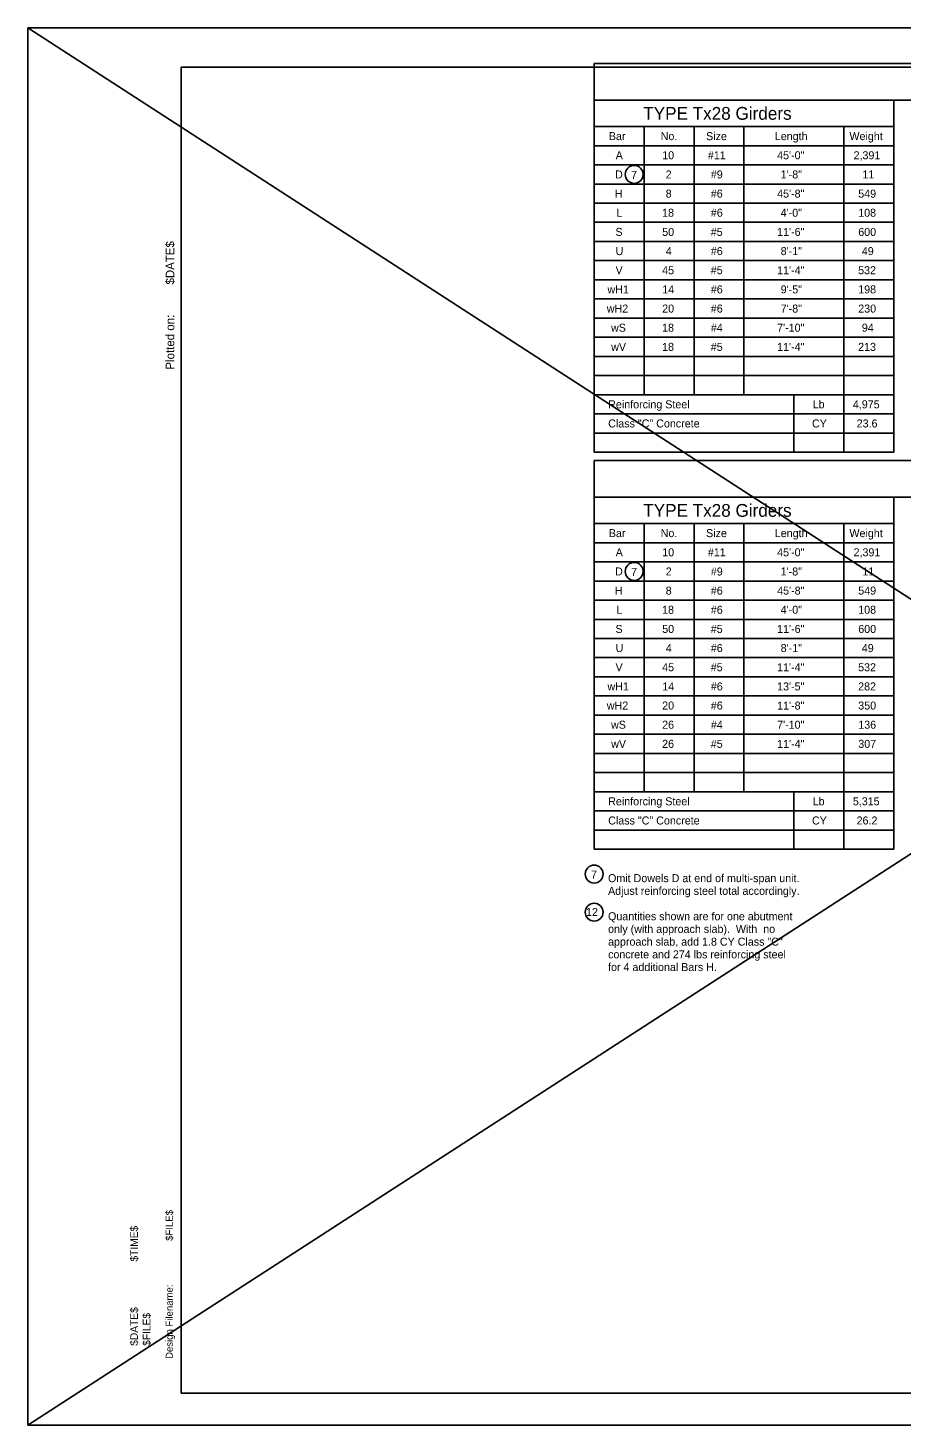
# Model space of a CAD drawing. Extents: x 926 to 1074, y 990 to 1081.
# Drawn here: x 1000 to 1013.75, y 1023 to 1045 of the extents above; entities that cross this region are included whole.
import ezdxf

# ---------------------------------------------------------------- set-up
doc = ezdxf.new("R2010")
doc.units = 0
for name, color, linetype in [('BORD_lines_major', 7, 'Continuous'), ('BORD_text_filename_date', 7, 'Continuous'), ('D_BATCH_PLOT', 7, 'Continuous'), ('D_SHEET', 7, 'Continuous'), ('D_SHEET_TXT_SUB_CODE', 7, 'Continuous'), ('Working Level 1', 7, 'Continuous')]:
    doc.layers.add(name, color=color, linetype=linetype)

msp = doc.modelspace()

# ---------------------------------------------------------------- linework, layer by layer
at = {"layer": 'BORD_lines_major'}
for p, q in [((1002.413, 1023.5), (1002.413, 1044.382)), ((1002.413, 1044.382), (1033.5, 1044.382)), ((1002.413, 1023.5), (1033.5, 1023.5))]:
    msp.add_line(p, q, dxfattribs=at)
at = {"layer": 'D_BATCH_PLOT'}
msp.add_lwpolyline([(1000, 1023), (1034, 1023), (1034, 1045), (1000, 1045)], close=True, dxfattribs=at)
at = {"layer": 'D_SHEET'}
for p, q in [((1000, 1045), (1034, 1045)), ((1000, 1023), (1000, 1045)), ((1000, 1023), (1034, 1023))]:
    msp.add_line(p, q, dxfattribs=at)
at = {"layer": 'Working Level 1'}
for p, q in [((1000, 1023), (1034, 1045)), ((1000, 1045), (1034, 1023)), ((1008.919, 1044.44), (1033.44, 1044.44)), ((1008.919, 1038.319), (1008.919, 1044.44)), ((1008.919, 1043.862), (1033.44, 1043.862)), ((1013.637, 1038.319), (1013.637, 1043.862)), ((1008.919, 1043.447), (1013.637, 1043.447)), ((1009.705, 1039.224), (1009.705, 1043.447)), ((1010.492, 1039.224), (1010.492, 1043.447)), ((1011.278, 1039.224), (1011.278, 1043.447)), ((1012.85, 1038.319), (1012.85, 1043.447)), ((1008.919, 1043.145), (1013.637, 1043.145)), ((1010.492, 1039.224), (1010.492, 1043.145)), ((1011.278, 1039.224), (1011.278, 1043.145)), ((1008.919, 1042.844), (1013.637, 1042.844)), ((1008.919, 1042.542), (1013.637, 1042.542)), ((1008.919, 1042.24), (1013.637, 1042.24)), ((1008.919, 1041.939), (1013.637, 1041.939)), ((1008.919, 1041.637), (1013.637, 1041.637)), ((1008.919, 1041.336), (1013.637, 1041.336)), ((1008.919, 1041.034), (1013.637, 1041.034)), ((1008.919, 1040.732), (1013.637, 1040.732)), ((1008.919, 1040.431), (1013.637, 1040.431)), ((1008.919, 1040.129), (1013.637, 1040.129)), ((1008.919, 1039.827), (1013.637, 1039.827)), ((1008.919, 1039.526), (1013.637, 1039.526)), ((1008.919, 1039.224), (1013.637, 1039.224)), ((1012.064, 1038.319), (1012.064, 1039.224)), ((1008.919, 1038.922), (1013.637, 1038.922)), ((1008.919, 1038.621), (1013.637, 1038.621)), ((1008.919, 1038.319), (1013.637, 1038.319)), ((1008.919, 1038.188), (1033.44, 1038.188)), ((1008.919, 1032.068), (1008.919, 1038.188)), ((1008.919, 1037.61), (1033.44, 1037.61)), ((1013.637, 1032.068), (1013.637, 1037.61)), ((1008.919, 1037.195), (1013.637, 1037.195)), ((1009.705, 1032.972), (1009.705, 1037.195)), ((1010.492, 1032.972), (1010.492, 1037.195)), ((1011.278, 1032.972), (1011.278, 1037.195)), ((1012.85, 1032.068), (1012.85, 1037.195)), ((1008.919, 1036.894), (1013.637, 1036.894)), ((1010.492, 1032.972), (1010.492, 1036.894)), ((1011.278, 1032.972), (1011.278, 1036.894)), ((1008.919, 1036.592), (1013.637, 1036.592)), ((1008.919, 1036.291), (1013.637, 1036.291)), ((1008.919, 1035.989), (1013.637, 1035.989)), ((1008.919, 1035.687), (1013.637, 1035.687)), ((1008.919, 1035.386), (1013.637, 1035.386)), ((1008.919, 1035.084), (1013.637, 1035.084)), ((1008.919, 1034.782), (1013.637, 1034.782)), ((1008.919, 1034.481), (1013.637, 1034.481)), ((1008.919, 1034.179), (1013.637, 1034.179)), ((1008.919, 1033.877), (1013.637, 1033.877)), ((1008.919, 1033.576), (1013.637, 1033.576)), ((1008.919, 1033.274), (1013.637, 1033.274)), ((1008.919, 1032.972), (1013.637, 1032.972)), ((1012.064, 1032.068), (1012.064, 1032.972)), ((1008.919, 1032.671), (1013.637, 1032.671)), ((1008.919, 1032.369), (1013.637, 1032.369)), ((1008.919, 1032.068), (1013.637, 1032.068))]:
    msp.add_line(p, q, dxfattribs=at)
for centre in [(1009.55, 1042.694), (1009.55, 1036.442), (1008.919, 1031.676), (1008.919, 1031.076)]:
    msp.add_circle(centre, 0.141, dxfattribs=at)

# ---------------------------------------------------------------- texts
at = {"layer": 'BORD_text_filename_date'}
for s, height, p in [('$DATE$', 0.135, (1002.305, 1040.96)), ('Plotted on:', 0.135, (1002.305, 1039.62)), ('$FILE$', 0.1126, (1002.282, 1025.901)), ('Design Filename:', 0.11256, (1002.282, 1024.041))]:
    msp.add_text(s, height=height, rotation=89.9834, dxfattribs=at).set_placement(p)
at = {"layer": 'D_SHEET_TXT_SUB_CODE'}
for s, p in [('$TIME$', (1001.732, 1025.575)), ('$DATE$', (1001.732, 1024.249)), ('$FILE$', (1001.929, 1024.248))]:
    msp.add_text(s, height=0.12, rotation=90, dxfattribs=at).set_placement(p)
at = {"layer": 'Working Level 1'}
for s, height, p in [('TYPE Tx28 Girders ', 0.2016, (1009.692, 1043.554)), ('Bar', 0.126, (1009.15, 1043.233)), ('No.', 0.126, (1009.967, 1043.233)), ('Size', 0.126, (1010.682, 1043.233)), ('Length', 0.126, (1011.765, 1043.233)), ('Weight', 0.126, (1012.94, 1043.233)), ('A', 0.126, (1009.258, 1042.932)), ('10', 0.126, (1009.991, 1042.932)), ('#11', 0.126, (1010.71, 1042.932)), ('45\'-0"', 0.126, (1011.801, 1042.932)), ('2,391', 0.126, (1013.005, 1042.932)), ('D', 0.126, (1009.248, 1042.63)), ('7', 0.126, (1009.501, 1042.623)), ('2', 0.126, (1010.046, 1042.63)), ('#9', 0.126, (1010.757, 1042.63)), ('1\'-8"', 0.126, (1011.857, 1042.63)), ('11', 0.126, (1013.145, 1042.63)), ('H', 0.126, (1009.245, 1042.328)), ('8', 0.126, (1010.046, 1042.328)), ('#6', 0.126, (1010.757, 1042.328)), ('45\'-8"', 0.126, (1011.801, 1042.328)), ('549', 0.126, (1013.079, 1042.328)), ('L', 0.126, (1009.268, 1042.027)), ('18', 0.126, (1009.989, 1042.027)), ('#6', 0.126, (1010.757, 1042.027)), ('4\'-0"', 0.126, (1011.857, 1042.027)), ('108', 0.126, (1013.078, 1042.027)), ('S', 0.126, (1009.254, 1041.725)), ('50', 0.126, (1009.991, 1041.725)), ('#5', 0.126, (1010.756, 1041.725)), ('11\'-6"', 0.126, (1011.801, 1041.725)), ('600', 0.126, (1013.079, 1041.725)), ('U', 0.126, (1009.257, 1041.423)), ('4', 0.126, (1010.048, 1041.423)), ('#6', 0.126, (1010.757, 1041.423)), ('8\'-1"', 0.126, (1011.857, 1041.423)), ('49', 0.126, (1013.135, 1041.423)), ('V', 0.126, (1009.256, 1041.122)), ('45', 0.126, (1009.99, 1041.122)), ('#5', 0.126, (1010.756, 1041.122)), ('11\'-4"', 0.126, (1011.801, 1041.122)), ('532', 0.126, (1013.077, 1041.122)), ('wH1', 0.126, (1009.129, 1040.82)), ('14', 0.126, (1009.992, 1040.82)), ('#6', 0.126, (1010.757, 1040.82)), ('9\'-5"', 0.126, (1011.857, 1040.82)), ('198', 0.126, (1013.078, 1040.82)), ('wH2', 0.126, (1009.118, 1040.518)), ('20', 0.126, (1009.991, 1040.518)), ('#6', 0.126, (1010.757, 1040.518)), ('7\'-8"', 0.126, (1011.857, 1040.518)), ('230', 0.126, (1013.079, 1040.518)), ('wS', 0.126, (1009.185, 1040.217)), ('18', 0.126, (1009.989, 1040.217)), ('#4', 0.126, (1010.758, 1040.217)), ('7\'-10"', 0.126, (1011.801, 1040.217)), ('94', 0.126, (1013.136, 1040.217)), ('wV', 0.126, (1009.187, 1039.915)), ('18', 0.126, (1009.989, 1039.915)), ('#5', 0.126, (1010.756, 1039.915)), ('11\'-4"', 0.126, (1011.801, 1039.915)), ('213', 0.126, (1013.077, 1039.915)), ('Reinforcing Steel', 0.126, (1009.14, 1039.01)), ('Lb', 0.126, (1012.361, 1039.01)), ('4,975', 0.126, (1012.994, 1039.01)), ('Class "C" Concrete', 0.126, (1009.14, 1038.709)), ('CY', 0.126, (1012.35, 1038.709)), ('23.6', 0.126, (1013.054, 1038.709)), ('TYPE Tx28 Girders ', 0.2016, (1009.692, 1037.302)), ('Bar', 0.126, (1009.15, 1036.982)), ('No.', 0.126, (1009.967, 1036.982)), ('Size', 0.126, (1010.682, 1036.982)), ('Length', 0.126, (1011.765, 1036.982)), ('Weight', 0.126, (1012.94, 1036.982)), ('A', 0.126, (1009.258, 1036.68)), ('10', 0.126, (1009.991, 1036.68)), ('#11', 0.126, (1010.71, 1036.68)), ('45\'-0"', 0.126, (1011.801, 1036.68)), ('2,391', 0.126, (1013.005, 1036.68)), ('D', 0.126, (1009.248, 1036.378)), ('7', 0.126, (1009.501, 1036.372)), ('2', 0.126, (1010.046, 1036.378)), ('#9', 0.126, (1010.757, 1036.378)), ('1\'-8"', 0.126, (1011.857, 1036.378)), ('11', 0.126, (1013.145, 1036.378)), ('H', 0.126, (1009.245, 1036.077)), ('8', 0.126, (1010.046, 1036.077)), ('#6', 0.126, (1010.757, 1036.077)), ('45\'-8"', 0.126, (1011.801, 1036.077)), ('549', 0.126, (1013.079, 1036.077)), ('L', 0.126, (1009.268, 1035.775)), ('18', 0.126, (1009.989, 1035.775)), ('#6', 0.126, (1010.757, 1035.775)), ('4\'-0"', 0.126, (1011.857, 1035.775)), ('108', 0.126, (1013.078, 1035.775)), ('S', 0.126, (1009.254, 1035.473)), ('50', 0.126, (1009.991, 1035.473)), ('#5', 0.126, (1010.756, 1035.473)), ('11\'-6"', 0.126, (1011.801, 1035.473)), ('600', 0.126, (1013.079, 1035.473)), ('U', 0.126, (1009.257, 1035.172)), ('4', 0.126, (1010.048, 1035.172)), ('#6', 0.126, (1010.757, 1035.172)), ('8\'-1"', 0.126, (1011.857, 1035.172)), ('49', 0.126, (1013.135, 1035.172)), ('V', 0.126, (1009.256, 1034.87)), ('45', 0.126, (1009.99, 1034.87)), ('#5', 0.126, (1010.756, 1034.87)), ('11\'-4"', 0.126, (1011.801, 1034.87)), ('532', 0.126, (1013.077, 1034.87)), ('wH1', 0.126, (1009.129, 1034.568)), ('14', 0.126, (1009.992, 1034.568)), ('#6', 0.126, (1010.757, 1034.568)), ('13\'-5"', 0.126, (1011.801, 1034.568)), ('282', 0.126, (1013.077, 1034.568)), ('wH2', 0.126, (1009.118, 1034.267)), ('20', 0.126, (1009.991, 1034.267)), ('#6', 0.126, (1010.757, 1034.267)), ('11\'-8"', 0.126, (1011.801, 1034.267)), ('350', 0.126, (1013.079, 1034.267)), ('wS', 0.126, (1009.185, 1033.965)), ('26', 0.126, (1009.99, 1033.965)), ('#4', 0.126, (1010.758, 1033.965)), ('7\'-10"', 0.126, (1011.801, 1033.965)), ('136', 0.126, (1013.079, 1033.965)), ('wV', 0.126, (1009.187, 1033.664)), ('26', 0.126, (1009.99, 1033.664)), ('#5', 0.126, (1010.756, 1033.664)), ('11\'-4"', 0.126, (1011.801, 1033.664)), ('307', 0.126, (1013.08, 1033.664)), ('Reinforcing Steel', 0.126, (1009.14, 1032.759)), ('Lb', 0.126, (1012.361, 1032.759)), ('5,315', 0.126, (1012.994, 1032.759)), ('Class "C" Concrete', 0.126, (1009.14, 1032.457)), ('CY', 0.126, (1012.35, 1032.457)), ('26.2', 0.126, (1013.053, 1032.457)), ('7', 0.126, (1008.87, 1031.606)), ('Omit Dowels D at end of multi-span unit.', 0.126, (1009.138, 1031.549)), ('Adjust reinforcing steel total accordingly.', 0.126, (1009.138, 1031.349)), ('12', 0.126, (1008.791, 1031.017)), ('Quantities shown are for one abutment', 0.126, (1009.138, 1030.949)), ('only (with approach slab).  With  no', 0.126, (1009.138, 1030.749)), ('approach slab, add 1.8 CY Class "C"', 0.126, (1009.138, 1030.549)), ('concrete and 274 lbs reinforcing steel', 0.126, (1009.138, 1030.349)), ('for 4 additional Bars H.', 0.126, (1009.138, 1030.149))]:
    msp.add_text(s, height=height, dxfattribs=at).set_placement(p)

doc.saveas('drawing.dxf')
